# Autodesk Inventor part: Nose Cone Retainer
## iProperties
Shininess: 70.0
Angle Display Precision: 2
Document Length Units: 11269
Document Angle Units: 11279
Document Time Units: 11290
Document Mass Units: 11283
Document Length Units Precision: 3
Document Angle Units Precision: 2
Compacted: True
Created: 2001-08
Part Number: Nose Cone Retainer
Document SubType Name: Sheet Metal
Designer: Martin Budgell
Density: 0.0
Volumn: 0.0
Area: 0.0
PropertySet Name: Model Information
Control State: 0
Master: False
Checked Out: False
Author: Martin Budgell
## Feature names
1. Corner Round1
2. Hole1
3. Plate1
4. Bend1
